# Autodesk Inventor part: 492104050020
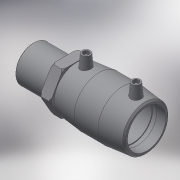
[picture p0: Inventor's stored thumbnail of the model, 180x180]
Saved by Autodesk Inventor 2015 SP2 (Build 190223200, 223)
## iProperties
Created: 2017-06
Part Number: 492104050020
Material: Generic
Description: PLASSON Male Transition Coupler 50 x 2"
Document SubType Name: Modeling
Designer: KIM
Mass: 294.504 g
Surface Area: 666.567 cm^2
Volume: 294.504 cm^3
Density: 1 g/cm^3
Appearance: Default
Author: KIM
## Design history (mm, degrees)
derived "492104.ipt"
feature "Solid1::492104.ipt"
tag "TaggingFeature1"
body "Solid1"
other parameters: "d0" = 119, "d2" = 69, "d3" = 49, "d4" = 39.66667, "d5" = 62.1, "d6" = 47.5, "d8" = 168 deg, "d10" = 19.6, "d11" = 6.53333, "d29" = 59, "d30" = 14, "d31" = 41.65, "d34" = 5 deg, "d41" = 4, "d42" = 14, "d43" = 0, "d48" = 3, "d49" = 0, "d57" = 38, "d58" = 59.614, "d59" = 47.6912, "d60" = 36.9, "d61" = 69, "d62" = 1.19228, "d65" = 2.07, "d70" = 0.1, "d71" = 41, "d72" = 10.25, "d73" = 19.6, "d75" = 0, "L_1" = 49, "D_1" = 69, "A_" = 59, "d_2" = 12, "L_2" = 41, "D_" = 38, "R_" = 59.614
